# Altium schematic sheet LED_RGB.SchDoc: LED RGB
size A4; SheetNumber: 11; SheetTotal: 11
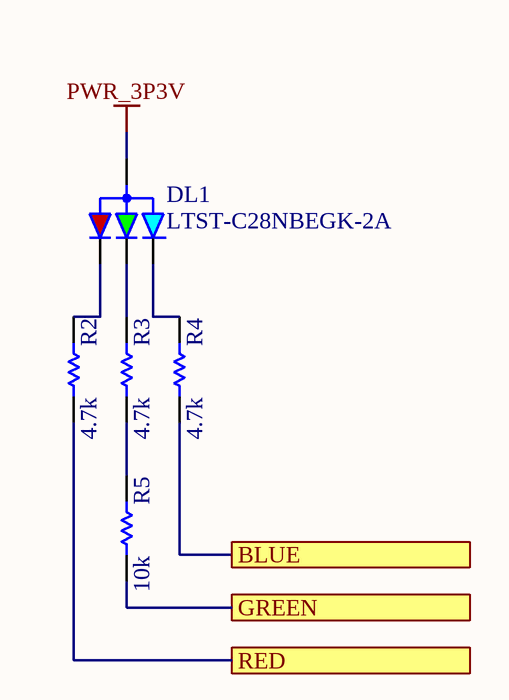
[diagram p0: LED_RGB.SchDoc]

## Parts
DL1  LTST-C28NBEGK-2A  [SMLP34RGB2W]
R2  value 4.7k  [RES-0402]  (hidden comment: RC0402FR-074K7L)
R3  value 4.7k  [RES-0402]  (hidden comment: RC0402FR-074K7L)
R4  value 4.7k  [RES-0402]  (hidden comment: RC0402FR-074K7L)
R5  value 10k  [RES-0402]  (hidden comment: CRCW040210K0FKED)

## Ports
BLUE, GREEN, RED

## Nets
PWR_3P3V: DL1.1(ANODE)
BLUE: R4.1 ; port BLUE
GREEN: R5.2 ; port GREEN
RED: R2.1 ; port RED
NetDL1_2: DL1.2(RED_C) R2.2
NetDL1_3: DL1.3(BLUE_C) R4.2
NetDL1_4: DL1.4(GREEN_C) R3.2
NetR3_1: R3.1 R5.1

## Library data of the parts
DL1 = L0014-A.13: LED RGB DIFFUSED PICOLED SMD; Manufacturer: Liteon; Code Arduino: A5469; Dominant Wavelength: 470nm; Forward Current: 20mA; Luminous Intensity: 45mcd; Forward Voltage: 3V; Lens Color: White; Lens Style: Rectangular; Test Current: 5mA
R2-R4 = R0013-A.24: RES CHIP 0402 4k7 1% 1/16W; Manufacturer: YAGEO; Code Arduino: 2196; Power: 62.5mW; Temperature coefficient: 200ppm
R5 = R0003-A.24: RES CHIP 0402 10k 1% 1/16W; Manufacturer: Vishay; Code Arduino: 0136; Power: 62.5mW; Temperature coefficient: 100ppm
